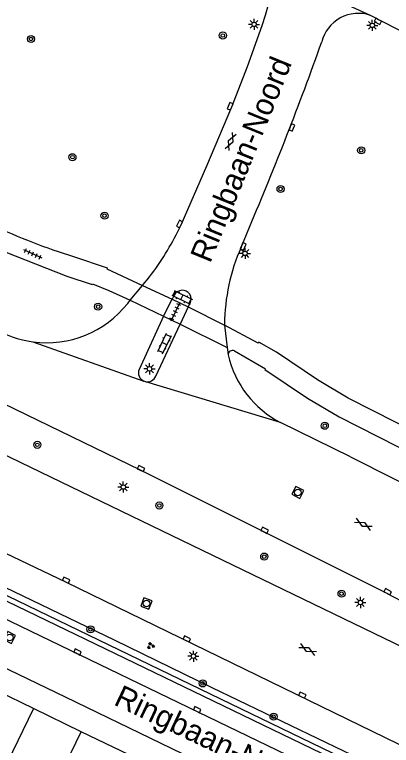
# Model space of a CAD drawing. Extents: x 132999 to 136000, y 398499 to 400501.
# Drawn here: x 134215 to 134257.5, y 398615.7 to 398698.2 of the extents above; entities that cross this region are included whole.
import ezdxf

# ---------------------------------------------------------------- set-up
doc = ezdxf.new("R2010")
doc.units = 0
for name, color, linetype in [('gg-anno-openbare ruimte label', 7, 'Continuous'), ('gg-bbg-hoofdgebouw', 7, 'Continuous'), ('gg-bbg-tussenscheiding', 7, 'Continuous'), ('gg-knt-verharding', 7, 'Continuous'), ('gg-knt-verharding nz', 7, 'Continuous'), ('gt-grn-groengrens', 7, 'Continuous'), ('gt-grn-weggrens', 7, 'Continuous'), ('gt-symb-boom', 7, 'Continuous'), ('gt-symb-gesloten verharding', 7, 'Continuous'), ('gt-symb-groenvak', 7, 'Continuous'), ('gt-symb-klinker verharding', 7, 'Continuous'), ('gt-symb-kolk', 7, 'Continuous'), ('gt-symb-lichtmast', 7, 'Continuous'), ('gt-symb-rioolschacht', 7, 'Continuous'), ('gt-symb-tegel verharding', 7, 'Continuous')]:
    doc.layers.add(name, color=color, linetype=linetype)

# ---------------------------------------------------------------- blocks, each defined once
blk = doc.blocks.new('gt0-KOLK')
at = {"layer": 'gt-symb-kolk'}
blk.add_lwpolyline([(0, 0), (0.375, 0), (0.375, 0.4), (-0.375, 0.4), (-0.375, 0), (0, 0)], dxfattribs=at)
blk = doc.blocks.new('gt0-BOOM')
at = {"layer": 'gt-symb-boom'}
for radius in [0.4, 0.2]:
    blk.add_circle((0, 0), radius, dxfattribs=at)
blk = doc.blocks.new('gt0-GESVH1')
at = {"layer": 'gt-symb-gesloten verharding'}
for p, q in [((-0.992, -0.261), (0.008, 0.239)), ((0.008, -0.261), (-0.992, 0.239)), ((0.008, 0.239), (1.008, -0.261)), ((1.008, 0.239), (0.008, -0.261))]:
    blk.add_line(p, q, dxfattribs=at)
blk = doc.blocks.new('gt0-LMAST')
at = {"layer": 'gt-symb-lichtmast'}
for p, q in [((-0.182, 0.173), (-0.447, 0.438)), ((-0.005, 0.246), (-0.005, 0.621)), ((0.172, 0.173), (0.437, 0.438)), ((-0.255, -0.004), (-0.63, -0.004)), ((-0.182, -0.181), (-0.447, -0.446)), ((-0.005, -0.254), (-0.005, -0.629)), ((0.437, -0.446), (0.172, -0.181)), ((0.245, -0.004), (0.62, -0.004))]:
    blk.add_line(p, q, dxfattribs=at)
blk.add_circle((-0.005, -0.004), 0.25, dxfattribs=at)
blk = doc.blocks.new('gt0-TEG1')
at = {"layer": 'gt-symb-tegel verharding'}
for p, q in [((-1.125, 0), (1.125, 0)), ((-0.9, -0.25), (-0.9, 0.25)), ((-0.45, -0.25), (-0.45, 0.25)), ((0, -0.25), (0, 0.25)), ((0.45, -0.25), (0.45, 0.25)), ((0.9, -0.25), (0.9, 0.25))]:
    blk.add_line(p, q, dxfattribs=at)
blk = doc.blocks.new('gt0-KL1')
at = {"layer": 'gt-symb-klinker verharding'}
for p, q in [((-1.15, 0.3), (1.15, 0.3)), ((-1, -0.3), (-1, 0.3)), ((-0.5, 0.3), (-0.5, 0.45)), ((0, -0.3), (0, 0.3)), ((0.5, 0.3), (0.5, 0.45)), ((1, -0.3), (1, 0.3)), ((-1.15, -0.3), (1.15, -0.3)), ((-0.5, -0.45), (-0.5, -0.3)), ((0.5, -0.45), (0.5, -0.3))]:
    blk.add_line(p, q, dxfattribs=at)
blk = doc.blocks.new('gt0-RS')
at = {"layer": 'gt-symb-rioolschacht'}
blk.add_lwpolyline([(-0.5, -0.5), (0.5, -0.5), (0.5, 0.5), (-0.5, 0.5)], close=True, dxfattribs=at)
blk.add_circle((0, 0), 0.375, dxfattribs=at)
blk = doc.blocks.new('gt0-GRVAK')
at = {"layer": 'gt-symb-groenvak'}
for p, q in [((-0.11, 0.189), (-0.228, 0.24)), ((-0.182, 0.153), (0.088, 0.153)), ((-0.091, 0.211), (-0.156, 0.322)), ((-0.047, 0.214), (-0.047, 0.393)), ((-0.004, 0.211), (0.061, 0.322)), ((0.015, 0.189), (0.133, 0.24)), ((0.262, -0.052), (0.197, 0.059)), ((0.305, -0.049), (0.305, 0.13)), ((0.349, -0.052), (0.414, 0.059)), ((-0.245, -0.228), (-0.363, -0.177)), ((-0.318, -0.264), (-0.047, -0.264)), ((-0.226, -0.206), (-0.291, -0.095)), ((-0.183, -0.203), (-0.183, -0.024)), ((-0.139, -0.206), (-0.074, -0.095)), ((-0.12, -0.228), (-0.002, -0.177)), ((0.243, -0.074), (0.125, -0.023)), ((0.17, -0.11), (0.441, -0.11)), ((0.368, -0.074), (0.486, -0.023))]:
    blk.add_line(p, q, dxfattribs=at)

msp = doc.modelspace()

# ---------------------------------------------------------------- linework, layer by layer
at = {"layer": 'gg-bbg-hoofdgebouw'}
for p, q in [((134217.071, 398619.829), (134213.029, 398621.783)), ((134222.474, 398617.218), (134217.071, 398619.829)), ((134227.885, 398614.602), (134222.474, 398617.218))]:
    msp.add_line(p, q, dxfattribs=at)
at = {"layer": 'gg-bbg-tussenscheiding'}
for p, q in [((134217.071, 398619.829), (134212.395, 398610.111)), ((134219.546, 398611.136), (134222.474, 398617.218))]:
    msp.add_line(p, q, dxfattribs=at)
at = {"layer": 'gg-knt-verharding'}
for p, q in [((134260.706, 398695.195), (134255.094, 398698.088)), ((134254.48, 398613.034), (134127.702, 398674.265)), ((134256.456, 398611.459), (134127.119, 398673.952)), ((134240.496, 398671.88), (134241.439, 398674.169)), ((134228.004, 398665.924), (134229.381, 398667.595)), ((134229.381, 398667.595), (134229.65, 398667.921)), ((134231.747, 398664.137), (134232.74, 398666.054)), ((134232.964, 398666.492), (134232.74, 398666.054)), ((134232.74, 398666.054), (134234.537, 398665.173)), ((134227.712, 398665.57), (134228.004, 398665.924)), ((134234.537, 398665.173), (134233.636, 398663.222)), ((134234.537, 398665.173), (134234.744, 398665.59)), ((134231.747, 398664.137), (134229.01, 398658.121)), ((134231.747, 398664.137), (134233.636, 398663.222)), ((134230.871, 398657.341), (134233.636, 398663.222)), ((134238.636, 398663.227), (134238.649, 398663.119)), ((134238.649, 398663.119), (134238.943, 398660.6)), ((134238.943, 398660.6), (134239.042, 398659.757)), ((134229.742, 398656.73), (134229.546, 398656.79)), ((134252.846, 398648.235), (134244.943, 398652.107)), ((134256.98, 398632.82), (134263.167, 398629.592))]:
    msp.add_line(p, q, dxfattribs=at)
for points in [[(134139.965, 398705.513), (134162.126, 398695.521), (134176.147, 398689.079), (134211.449, 398672.334), (134220.853, 398668.628), (134223.712, 398667.699), (134223.748, 398667.784), (134225.592, 398667.033), (134228.004, 398665.924)], [(134233.17, 398673.326), (134233.731, 398674.448), (134236.632, 398681.084), (134239.454, 398687.755), (134241.224, 398692.331), (134242.894, 398696.945), (134243.275, 398698.122), (134243.586, 398699.319)], [(134256.98, 398632.82), (134229.16, 398646.73), (134202.1, 398659.86), (134188.98, 398666.12), (134175.841, 398672.25), (134150.682, 398683.766)], [(134147.5, 398676.762), (134165.998, 398667.895), (134167.049, 398667.533), (134168.127, 398667.26), (134179.894, 398664.718), (134180.631, 398664.498), (134181.34, 398664.198), (134261.142, 398625.61)], [(134221.615, 398670.88), (134225.399, 398669.571), (134225.365, 398669.458), (134229.381, 398667.595)], [(134123.324, 398668.128), (134220.648, 398621.136), (134255.434, 398604.287)], [(134252.587, 398654.882), (134249.131, 398656.925), (134244.482, 398660.058), (134242.517, 398661.209), (134242.446, 398661.083), (134238.649, 398663.119)], [(134239.749, 398660.202), (134243.25, 398658.192), (134243.181, 398658.093), (134247.991, 398654.867), (134251.559, 398652.771), (134275.662, 398640.51), (134275.723, 398640.609), (134280.24, 398638.36)], [(134279.817, 398640.951), (134276.653, 398642.559), (134276.696, 398642.644), (134252.587, 398654.882)], [(134252.846, 398648.235), (134277.02, 398636.07), (134279.023, 398635.218)], [(134200.213, 398643.926), (134220.685, 398634.147), (134269.737, 398610.247)]]:
    msp.add_lwpolyline(points, dxfattribs=at)
for centre, radius, start, end in [((134253.726, 398694.056), 4.258, 71.26159, 166.02354), ((133909.205, 398815.758), 361.146, 336.91759, 340.47964), ((134239.165, 398729.464), 61.156, 244.10934, 253.32321), ((134207.789, 398686.007), 28.372, 320.39898, 333.45274), ((134260.377, 398663.08), 21.742, 156.1245, 179.61274), ((134233.866, 398666.065), 0.998, 331.60645, 154.64709), ((134218.571, 398672.752), 11.625, 262.33389, 321.84245), ((134218.571, 398672.753), 11.626, 238.62567, 262.33457), ((134239.532, 398659.762), 0.49, 63.78195, 180.59232), ((134250.333, 398662.366), 11.588, 193.00894, 242.28227), ((134229.936, 398657.721), 1.009, 156.61421, 247.25555), ((134229.935, 398657.721), 1.01, 258.96016, 337.88318)]:
    msp.add_arc(centre, radius, start, end, dxfattribs=at)
at = {"layer": 'gg-knt-verharding nz'}
for p, q in [((134229.381, 398667.595), (134232.74, 398666.054)), ((134228.004, 398665.924), (134231.747, 398664.137)), ((134234.537, 398665.173), (134238.649, 398663.119)), ((134233.636, 398663.222), (134238.943, 398660.6))]:
    msp.add_line(p, q, dxfattribs=at)
msp.add_lwpolyline([(134255.735, 398609.702), (134198.876, 398637.194), (134126.254, 398672.227)], dxfattribs=at)
at = {"layer": 'gt-grn-groengrens'}
msp.add_lwpolyline([(134197.263, 398641.53), (134226.169, 398627.587), (134237.199, 398622.193), (134252.051, 398615.044), (134256.521, 398612.928), (134268.493, 398606.699)], dxfattribs=at)
at = {"layer": 'gt-grn-weggrens'}
for p, q in [((134255.094, 398698.088), (134241.086, 398704.47)), ((134217.02, 398661.231), (134229.546, 398656.79)), ((134244.943, 398652.107), (134229.742, 398656.73))]:
    msp.add_line(p, q, dxfattribs=at)

# ---------------------------------------------------------------- block references
at = {"layer": 'gt-symb-boom'}
for p in [(134216.813, 398695.425), (134238.444, 398695.821), (134221.479, 398682.075), (134254.049, 398682.85), (134244.957, 398678.49), (134225.1, 398675.471), (134224.378, 398665.203), (134249.943, 398651.756), (134217.52, 398649.6), (134231.284, 398642.752), (134243.114, 398636.986), (134251.836, 398632.793), (134223.517, 398628.774), (134236.178, 398622.667), (134244.165, 398618.913)]:
    msp.add_blockref('gt0-BOOM', p, dxfattribs=at)
at = {"layer": 'gt-symb-gesloten verharding'}
for p, rotation in [((134239.316, 398683.851), 67.04963698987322), ((134254.3, 398640.636), -27.64114231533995), ((134248.004, 398626.504), -27.641142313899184)]:
    msp.add_blockref('gt0-GESVH1', p, dxfattribs=dict(at, rotation=rotation))
at = {"layer": 'gt-symb-groenvak'}
msp.add_blockref('gt0-GRVAK', (134230.292, 398626.916), dxfattribs=at)
at = {"layer": 'gt-symb-klinker verharding'}
for p, rotation in [((134233.844, 398666.266), -26.103824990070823), ((134231.869, 398661.037), 64.40857585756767)]:
    msp.add_blockref('gt0-KL1', p, dxfattribs=dict(at, rotation=rotation))
at = {"layer": 'gt-symb-kolk'}
for p, rotation in [((134256.017, 398697.601), 152.82026578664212), ((134239.454, 398687.755), 68.3580995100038), ((134246.045, 398685.506), -111.15264520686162), ((134233.731, 398674.448), 63.691304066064), ((134240.555, 398672.088), -113.02549200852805), ((134229.134, 398646.743), -26.488178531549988), ((134243.074, 398639.773), -26.667502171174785), ((134220.685, 398634.147), -25.539732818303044), ((134256.936, 398632.84), -27.12876606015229), ((134234.299, 398627.514), -25.975714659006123), ((134221.969, 398626.03), -25.79602649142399), ((134247.322, 398621.168), -25.975714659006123), ((134235.46, 398619.519), -25.84761021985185)]:
    msp.add_blockref('gt0-KOLK', p, dxfattribs=dict(at, rotation=rotation))
at = {"layer": 'gt-symb-lichtmast'}
for p in [(134241.972, 398697.077), (134255.31, 398696.962), (134240.951, 398671.217), (134230.178, 398658.185), (134227.226, 398644.841), (134253.966, 398631.803), (134235.128, 398625.743)]:
    msp.add_blockref('gt0-LMAST', p, dxfattribs=at)
at = {"layer": 'gt-symb-rioolschacht'}
for p, rotation in [((134246.903, 398644.232), -117.25687177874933), ((134229.825, 398631.688), 159.2092747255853), ((134214.402, 398627.84), 63.255579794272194)]:
    msp.add_blockref('gt0-RS', p, dxfattribs=dict(at, rotation=rotation))
at = {"layer": 'gt-symb-tegel verharding'}
for p, rotation in [((134217, 398671.171), -24.847205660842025), ((134233.102, 398664.62), 64.02428534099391)]:
    msp.add_blockref('gt0-TEG1', p, dxfattribs=dict(at, rotation=rotation))

# ---------------------------------------------------------------- texts
at = {"layer": 'gg-anno-openbare ruimte label'}
for rotation, p in [(67.8, (134237.008, 398670.02)), (334.7, (134226.019, 398620.307))]:
    msp.add_text('Ringbaan-Noord', height=2.5, rotation=rotation, dxfattribs=at).set_placement(p)

doc.saveas('drawing.dxf')
